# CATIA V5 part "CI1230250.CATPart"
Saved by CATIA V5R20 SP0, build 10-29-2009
Part number: CI1230250
Bounding box of the stored display mesh (mm): x -29 to 29, y -25.653 to 295, z -33.725 to 34.027
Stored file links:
  C:\Users\Raffaele\Desktop\3D X SITO CF\BOLEX\19-INCLINED ASSEMBLY REF_CI\CI1230250.CATPart
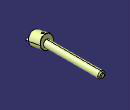
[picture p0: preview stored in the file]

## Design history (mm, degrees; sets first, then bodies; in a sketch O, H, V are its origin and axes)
Set1
  DatumSurface1 to DatumSurface16 "MANIFOLD_SOLID_BREP #399"
  DatumSurface17 to DatumSurface39 "MANIFOLD_SOLID_BREP #1148"
Body1 (main body)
